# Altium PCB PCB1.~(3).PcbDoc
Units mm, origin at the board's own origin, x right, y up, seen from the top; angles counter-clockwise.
Board outline 70 x 70 mm, 4 copper layers (Top Layer, Internal Plane 1, Internal Plane 2, Bottom Layer), stack 0.462 mm thick; 13 components, 15 nets, 56 pads, 0 vias.
Unrouted connection lines stored in the file: 38.
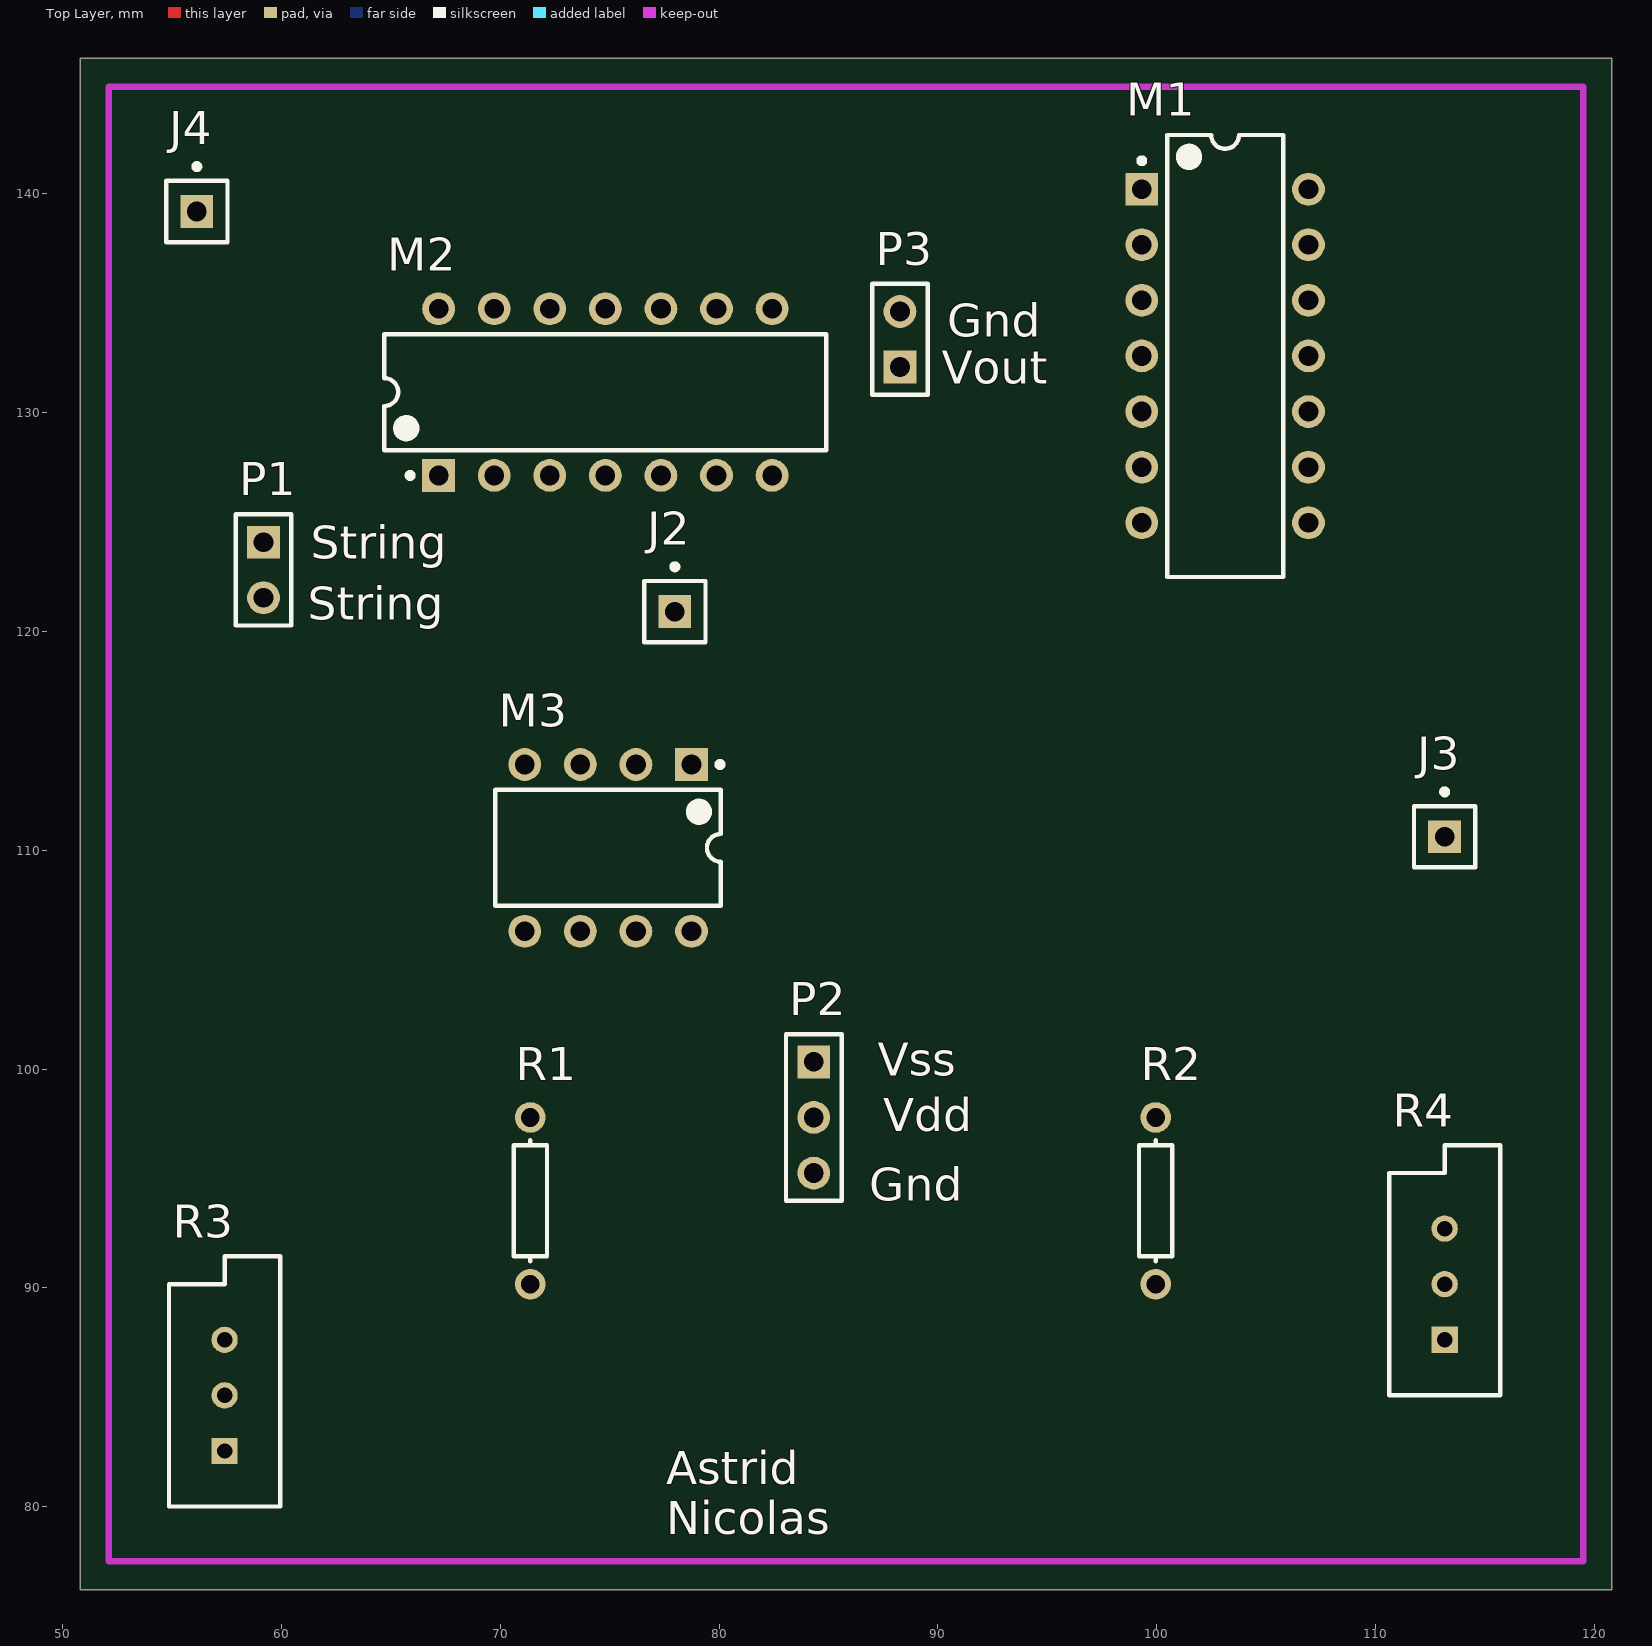
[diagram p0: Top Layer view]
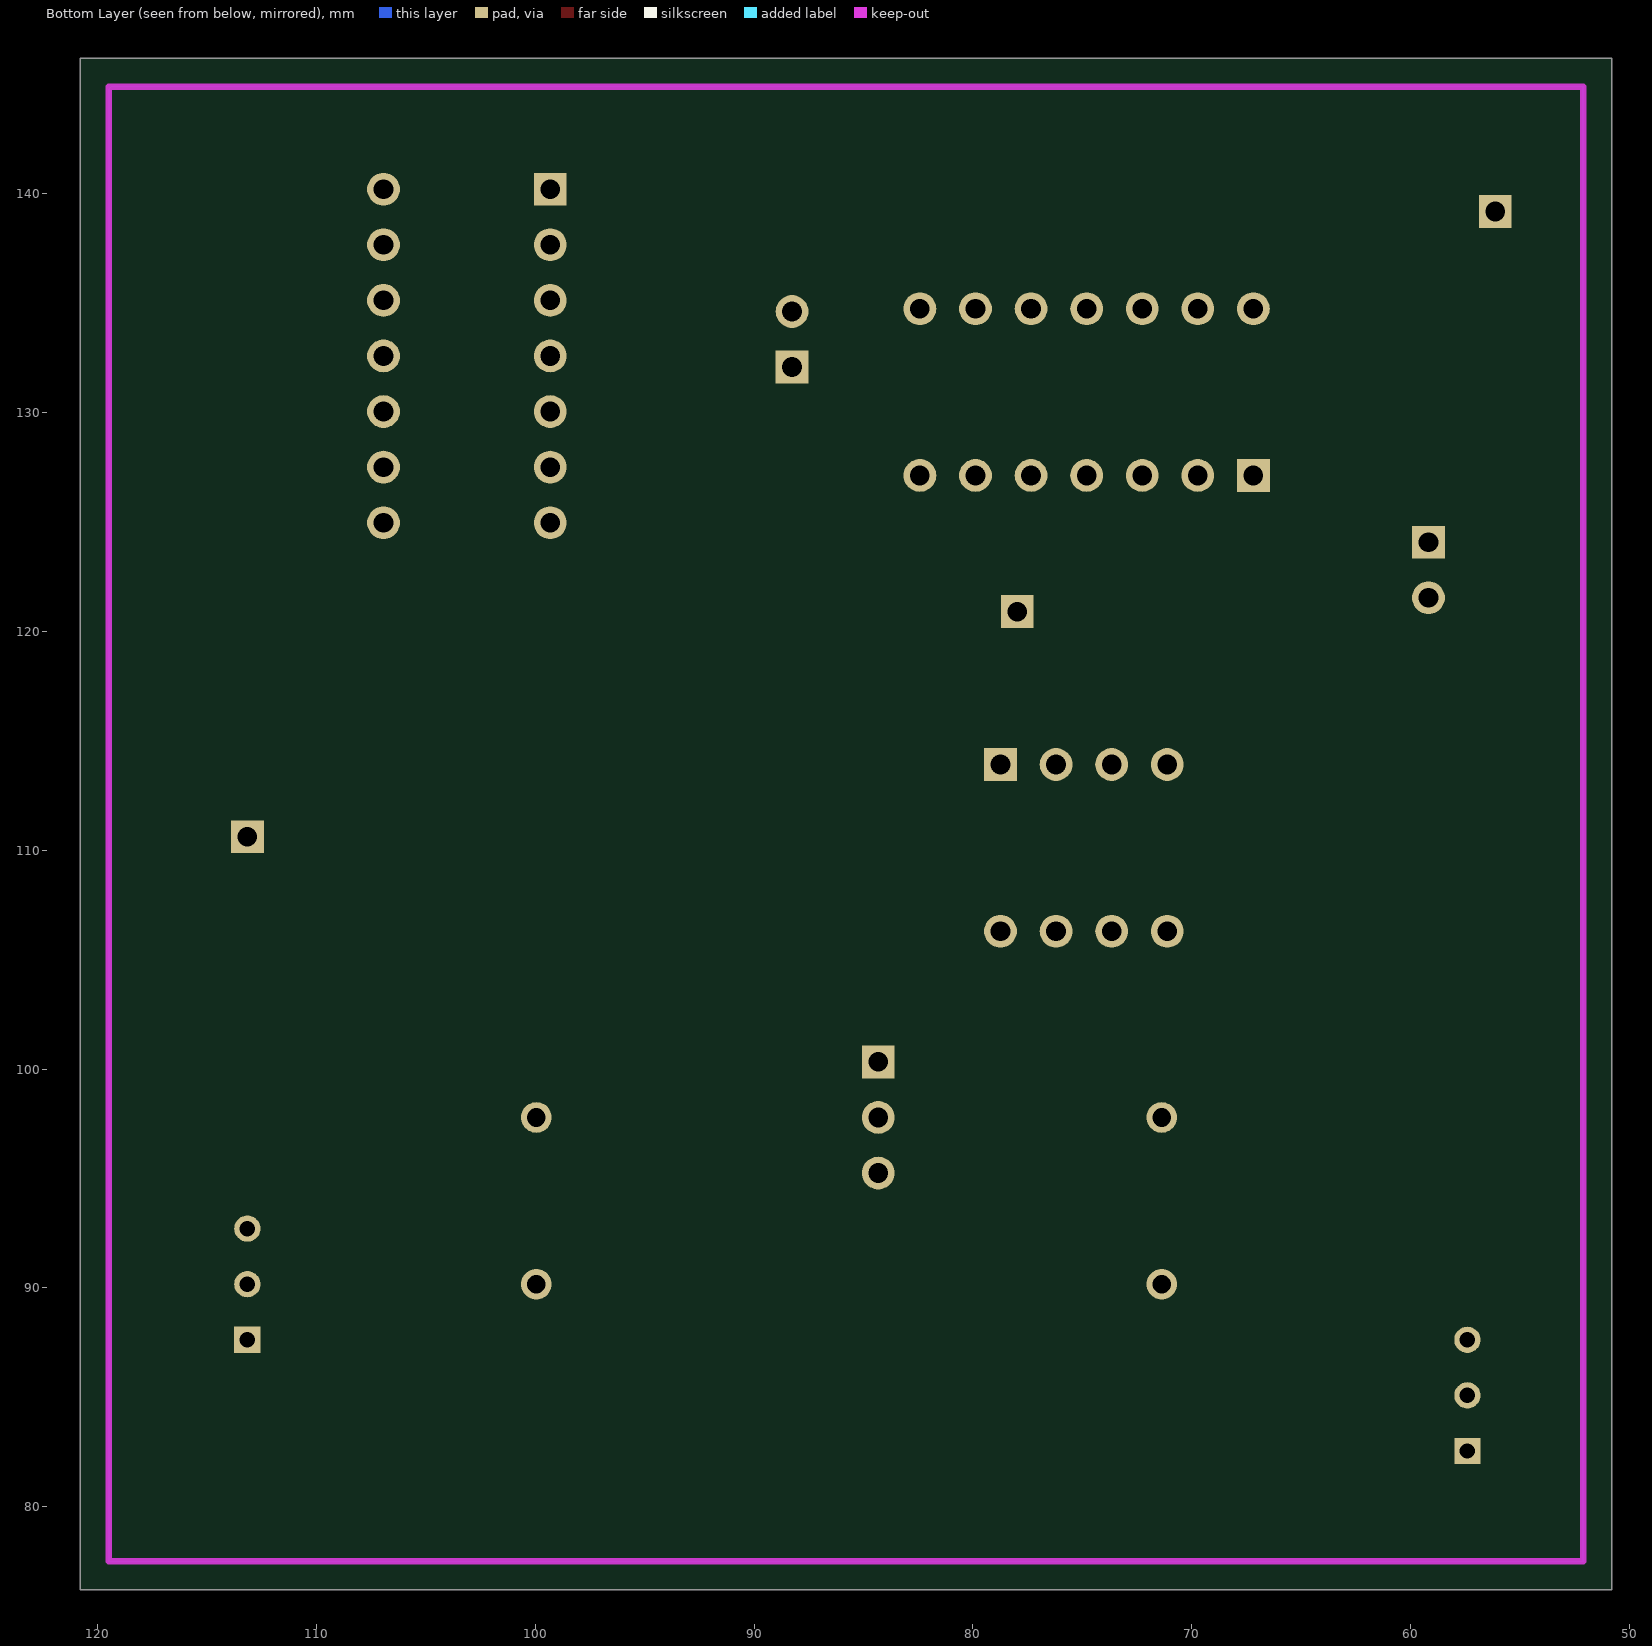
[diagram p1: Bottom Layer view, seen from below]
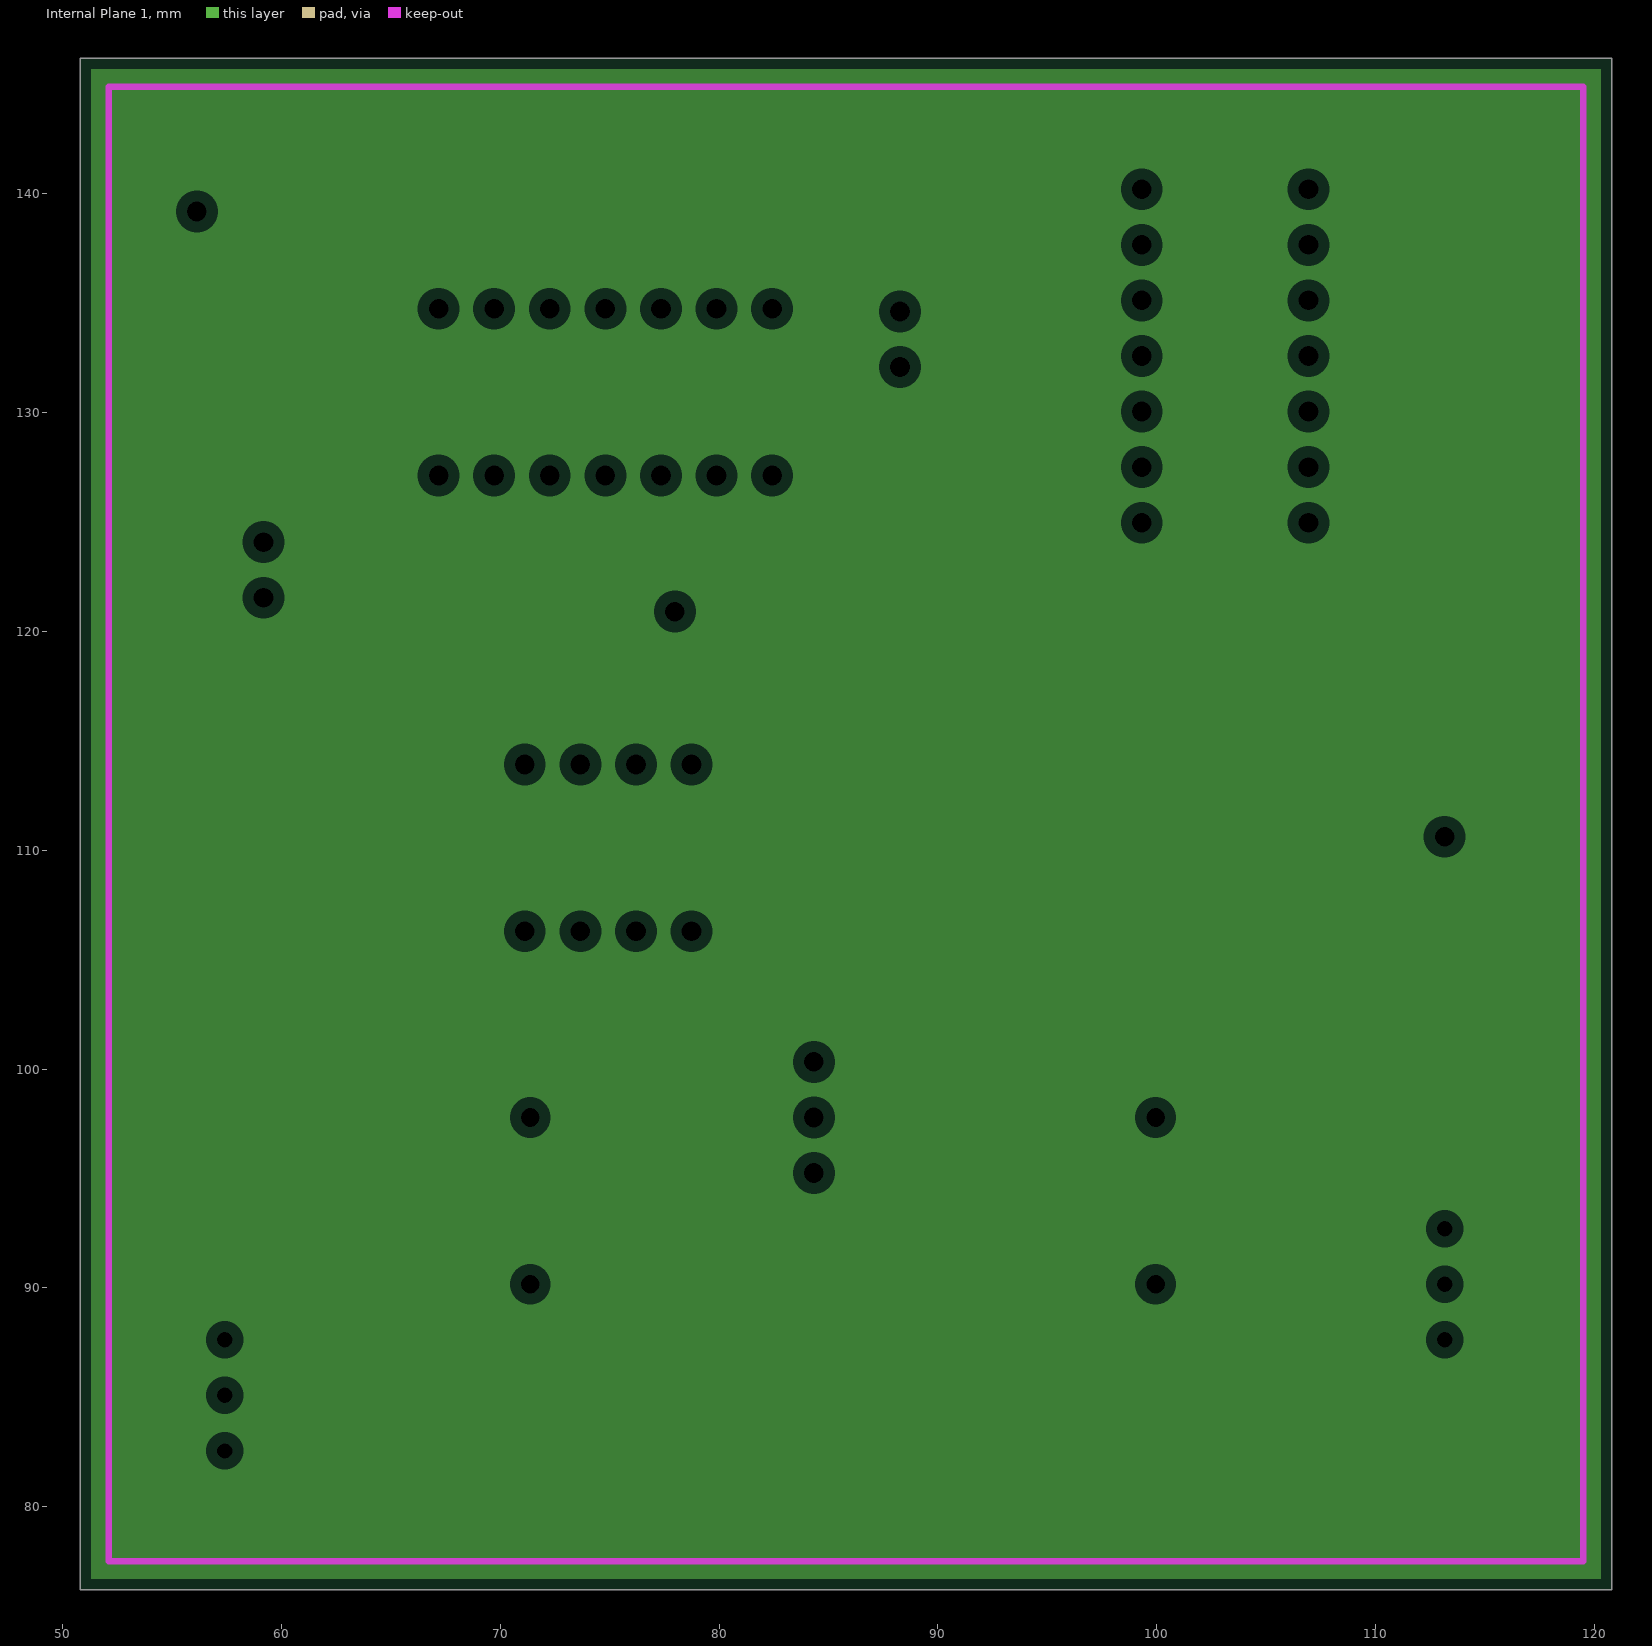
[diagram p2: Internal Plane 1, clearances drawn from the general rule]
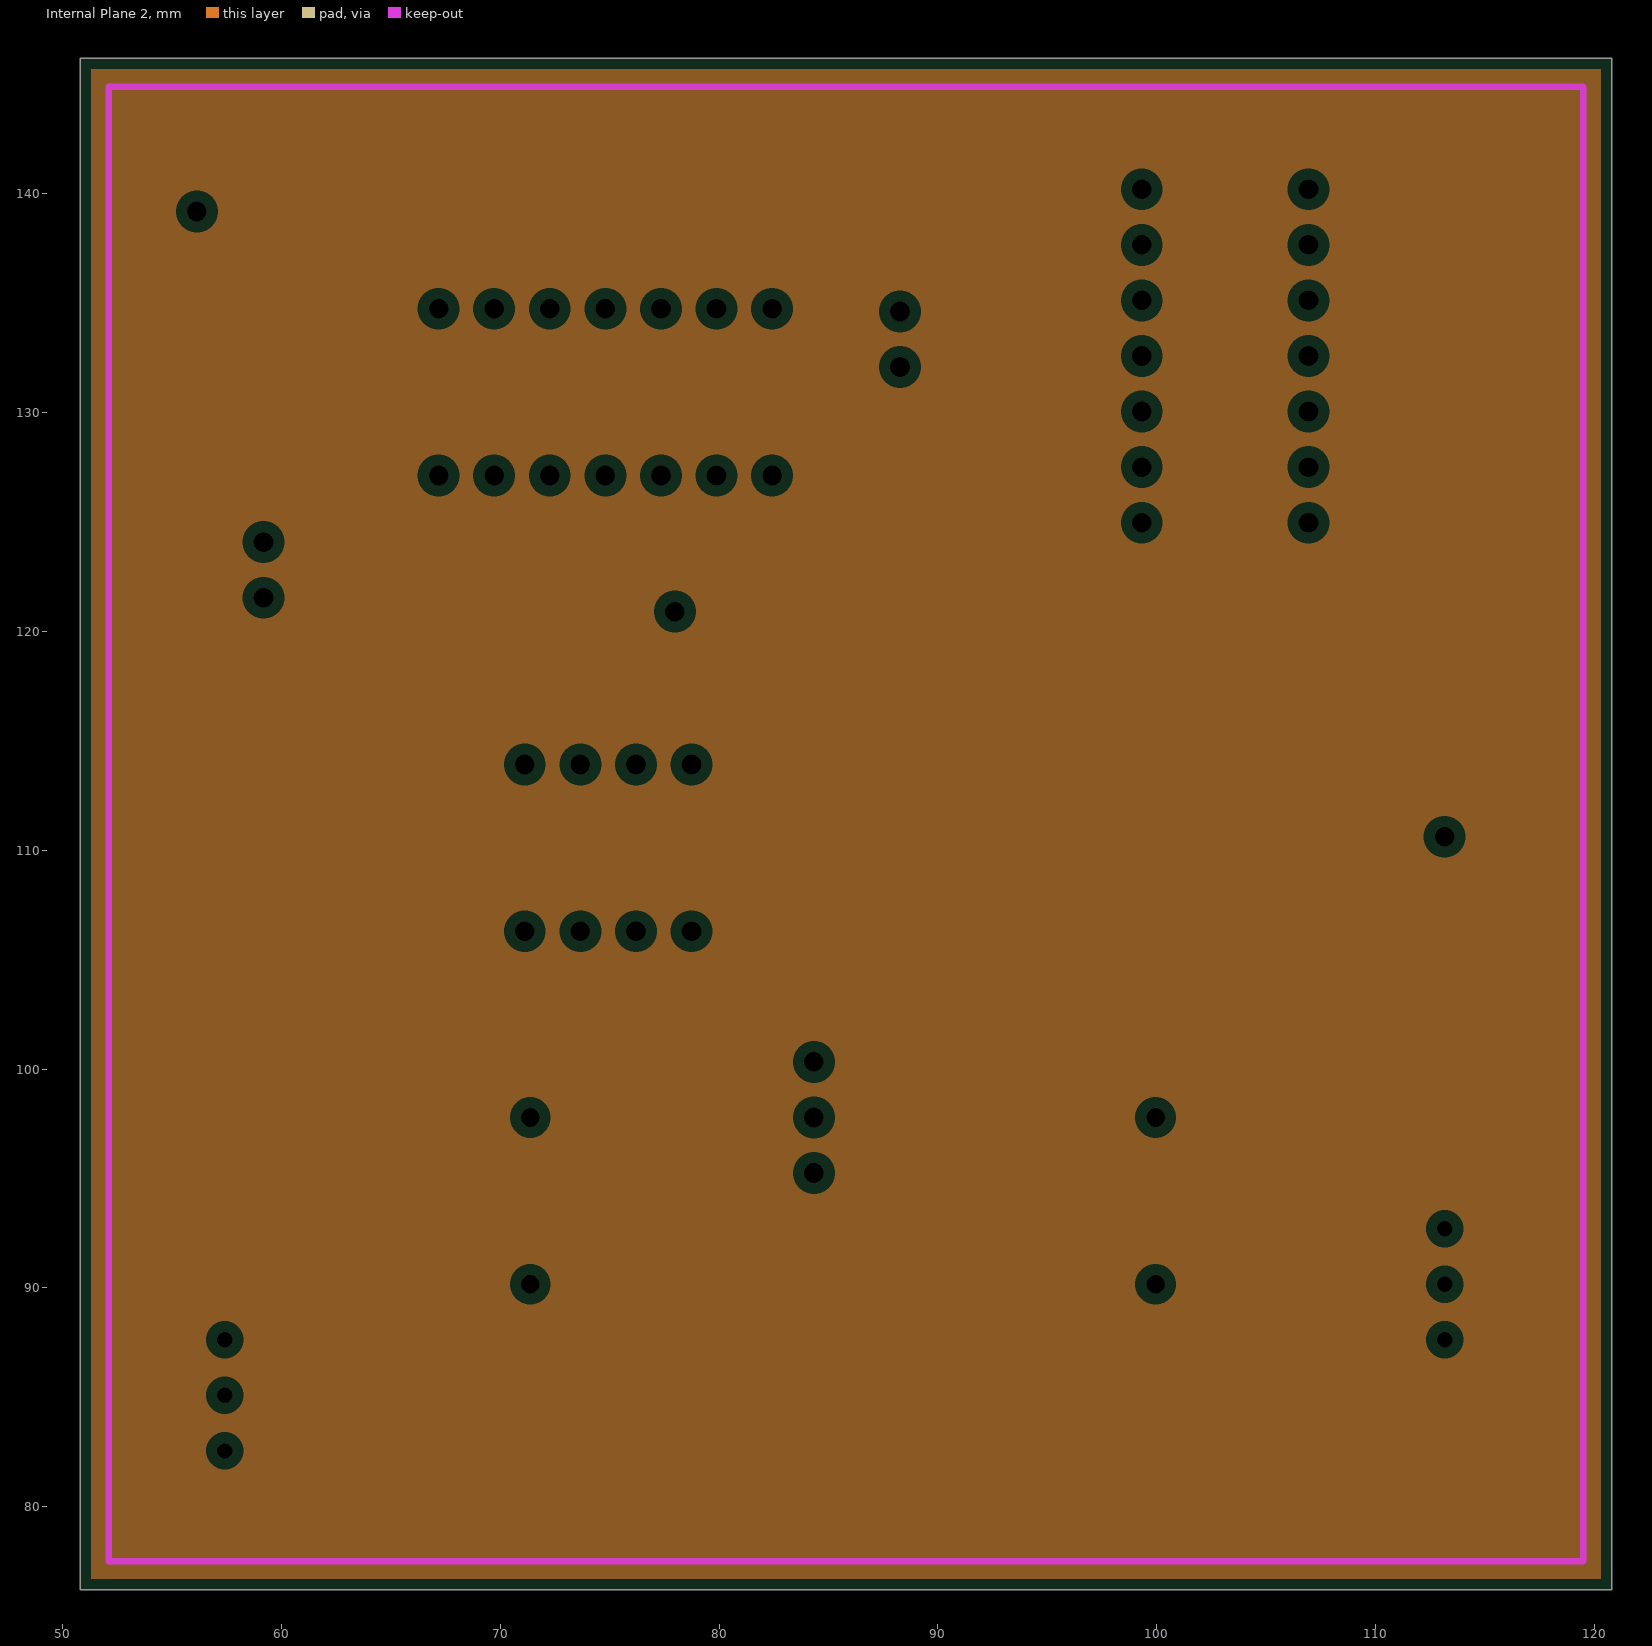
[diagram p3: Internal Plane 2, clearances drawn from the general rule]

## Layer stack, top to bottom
Top Solder: solder mask 0.0102, Solder Resist, Dk 3.5
Top Layer: signal copper 0.0356
Internal Plane 1: plane copper 0.0356
Internal Plane 2: plane copper 0.0356
Dielectric 1: dielectric 0.32, FR-4, Dk 4.8
Bottom Layer: signal copper 0.0356
Bottom Solder: solder mask 0.0102, Solder Resist, Dk 3.5

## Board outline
50.8,76.2 120.8,76.2 120.8,146.2 50.8,146.2

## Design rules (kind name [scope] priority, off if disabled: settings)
Clearance [All] p1: gap=0.8
PlaneClearance [All] p1: clearance=0.508
PlaneConnect [All] p1: planeconnectstyle=Relief reliefexpansion=0.508 reliefentries=4 reliefconductorwidth=0.254 reliefairgap=0.254
PolygonConnect [All] p1: connectstyle=Relief reliefconductorwidth=0.254 reliefentries=4 polygonreliefangle="90 Angle" airgapwidth=0.254
RoutingVias [All] p1: holewidth=0.8 width=1.6 viastyle="Through Hole" minholewidth=0.711 minwidth=1.27 maxholewidth=0.711 maxwidth=1.27
SolderMaskExpansion [All] p1: expansion=0.102
Width [All] p1: maxlimit=0.5 minlimit=0.5 preferedwidth=0.5
28 further rules are at their usual default settings.

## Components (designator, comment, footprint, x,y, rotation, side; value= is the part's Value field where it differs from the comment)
J2 "Socket" PIN1 77.978,120.904 r0 top
J3 "Socket" PIN1 113.157,110.617 r0 top
J4 "Socket" PIN1 56.134,139.192 r0 top
M1 "ALD1106" DIP-14 103.124,132.588 r0 top
M2 "ALD1105" DIP-14 74.803,130.937 r90 top
M3 "ALD1117" DIP-8 74.93,110.109 r270 top
P1 "Header 2" HDR1X2 59.182,124.079 r270 top
P2 "Header 3" HDR1X3 84.328,100.33 r270 top
P3 "Header 2" HDR1X2 88.265,132.08 r90 top
R1 "Res1" AXIAL-0.3 71.374,93.98 r90 top
R2 "Res1" AXIAL-0.3 99.949,93.98 r90 top
R3 "RPot" VR5 57.404,85.09 r90 top
R4 "RPot" VR5 113.157,90.17 r90 top

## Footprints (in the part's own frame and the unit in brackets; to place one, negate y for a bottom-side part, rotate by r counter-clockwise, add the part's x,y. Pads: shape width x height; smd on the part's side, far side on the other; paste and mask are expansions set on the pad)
AXIAL-0.3 [mm] "Axial Device, Thru-Hole; 2 Leads; 0.3 in Pin Spacing"
  round 1.4 hole 0.85: 1(-3.81,0) 2(3.81,0)
  silkscreen extent -2.77,-0.76 2.77,0.76
DIP-8 [mm] "DIP, 8-Pin, Row Spacing 7.62 mm, Pitch 2.54 mm"
  rect 1.5x1.5 hole 0.9: 1(-3.81,3.81)
  round 1.5 hole 0.9: 2(-3.81,1.27) 3(-3.81,-1.27) 4(-3.81,-3.81) 5(3.81,-3.81) 6(3.81,-1.27) 7(3.81,1.27) 8(3.81,3.81)
  silkscreen extent -3.93,-5.15 2.65,5.24, body extent -3.6,-5.15 3.6,5.15, height 5.33
DIP-14 [mm] "DIP, 14-Pin, Row Spacing 7.62 mm, Pitch 2.54 mm"
  rect 1.5x1.5 hole 0.9: 1(-3.81,7.62)
  round 1.5 hole 0.9: 2(-3.81,5.08) 3(-3.81,2.54) 4(-3.81,0) 5(-3.81,-2.54) 6(-3.81,-5.08) 7(-3.81,-7.62) 8(3.81,-7.62) 9(3.81,-5.08) 10(3.81,-2.54) 11(3.81,0) 12(3.81,2.54) 13(3.81,5.08) 14(3.81,7.62)
  silkscreen extent -3.93,-10.1 2.65,10.1, body extent -3.6,-10.1 3.6,10.1, height 5.08
HDR1X2 [mm] "Connector; Header; 2 Position"
  rect 1.5x1.5 hole 0.9: 1(0,0)
  round 1.5 hole 0.9: 2(2.54,0)
  silkscreen extent -1.27,-1.27 3.81,1.27
HDR1X3 [mm] "Connector; Header; 3 Position"
  rect 1.5x1.5 hole 0.9: 1(0,0)
  round 1.5 hole 0.9: 2(2.54,0) 3(5.08,0)
  silkscreen extent -1.27,-1.27 6.35,1.27
PIN1 [mm] "Connector; Plug"
  rect 1.5x1.5 hole 0.9: 1(0,0)
  silkscreen extent -1.4,-1.4 1.4,2.17
VR5 [mm] "Thru-Hole; 3 Leads"
  rect 1.2x1.2 hole 0.7: 1(-2.54,0)
  round 1.2 hole 0.7: 2(0,0) 3(2.54,0)
  silkscreen extent -5.08,-2.54 6.35,2.54

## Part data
M1: "Quad N-channel matched MOSFET array"
M2: "Dual P-channel and dual N-channel matched MOSFET array"
M3: "Dual P-channel matched MOSFET array"
P1 P3: "Header, 2-Pin"
P2: "Header, 3-Pin"
R1 R2: "Resistor"
R3 R4: "Potentiometer"

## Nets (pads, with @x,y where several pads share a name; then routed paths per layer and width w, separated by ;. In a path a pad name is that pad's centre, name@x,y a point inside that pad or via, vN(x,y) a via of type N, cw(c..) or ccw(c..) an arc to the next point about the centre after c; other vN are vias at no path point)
GND: P2.3 P3.2
IN+: M2.2 P1.2
IN-: M2.13 P1.1
NetJ2_1: J2.1 M2.1 M2.5 M3.2
NetJ3_1: J3.1 M1.5 M1.6 M1.9 R4.3
NetJ4_1: J4.1 M1.1 R3.2 R3.3
NetM1_2: M1.2 M1.13
NetM1_14: M1.14 M2.3 M2.4 M2.12
NetM2_6: M2.6 M2.9 M2.10 M2.14
NetM3_5: M3.6 M3.7 M3.8
NetR1_1: R1.1 R3.1
NetR2_1: R2.1 R4.1 R4.2
VDD: M2.7 M2.8 M2.11 M3.3 M3.5 P2.2 R1.2 R2.2
VOUT: M1.10 M3.1 P3.1
VSS: M1.3 M1.4 M1.7 M1.8 M1.12 P2.1
pads on no net: M1.11 M3.4

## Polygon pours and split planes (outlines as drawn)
GND on Bottom Layer "Bottom ground layer" (solid, shelved, pour order 2): 52.1,144.9 119.38,144.9 119.5,144.78 119.5,77.5 52.1,77.5

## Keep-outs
Keep-Out Layer:
  lines w0.3: 52.1,77.5 119.5,77.5 119.5,144.9 52.1,144.9 52.1,77.5

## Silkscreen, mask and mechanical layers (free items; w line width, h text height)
Top Overlay:
  text "Gnd" at 90.424,133.477 h1.52
  text "Vout" at 90.17,131.318 h1.52
  text "String" at 61.341,123.317 h1.52
  text "String" at 61.214,120.523 h1.52
  text "Vss" at 87.249,99.695 h1.52
  text "Vdd" at 87.503,97.155 h1.52
  text "Gnd" at 86.868,93.98 h1.52
  text "Astrid / Nicolas" at 77.597,78.74 h1.52

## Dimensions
52.1,77.5 to 119.5,77.5 on Mechanical 1
52.1,77.5 to 52.1,144.9 on Mechanical 1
